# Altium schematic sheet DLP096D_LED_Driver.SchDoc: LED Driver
size 431 x 279 mm; Date: Not shown in title block; ApprovedBy: Not shown in title block; CheckedBy: Not shown in title block; Author: Not shown in title block; CompanyName: Not shown in title block; Engineer: Not shown in title block; Organization: Not shown in title block; Address1: Not shown in title block; Address2: Not shown in title block; Address3: Not shown in title block; Address4: Not shown in title block; DocumentNumber: 9; Revision: Use project parameter SCH_Rev; SheetNumber: 9; SheetTotal: 10; PageSetup: Record=PageOptions¦CenterHorizontal=True¦CenterVertical=True¦PrintScale=1.00¦XCorrection=1.00¦YCorrection=1.00¦PrintKind=0¦BorderSize=5000000¦LeftOffset=0¦BottomOffset=0¦Orientation=2¦PaperLength=1000¦PaperWidth=1000¦Scale=100¦PaperSource=15¦PrintQuality=600¦MediaType=1¦DitherType=10¦PaperKind=Letter¦PrintScaleMode=1
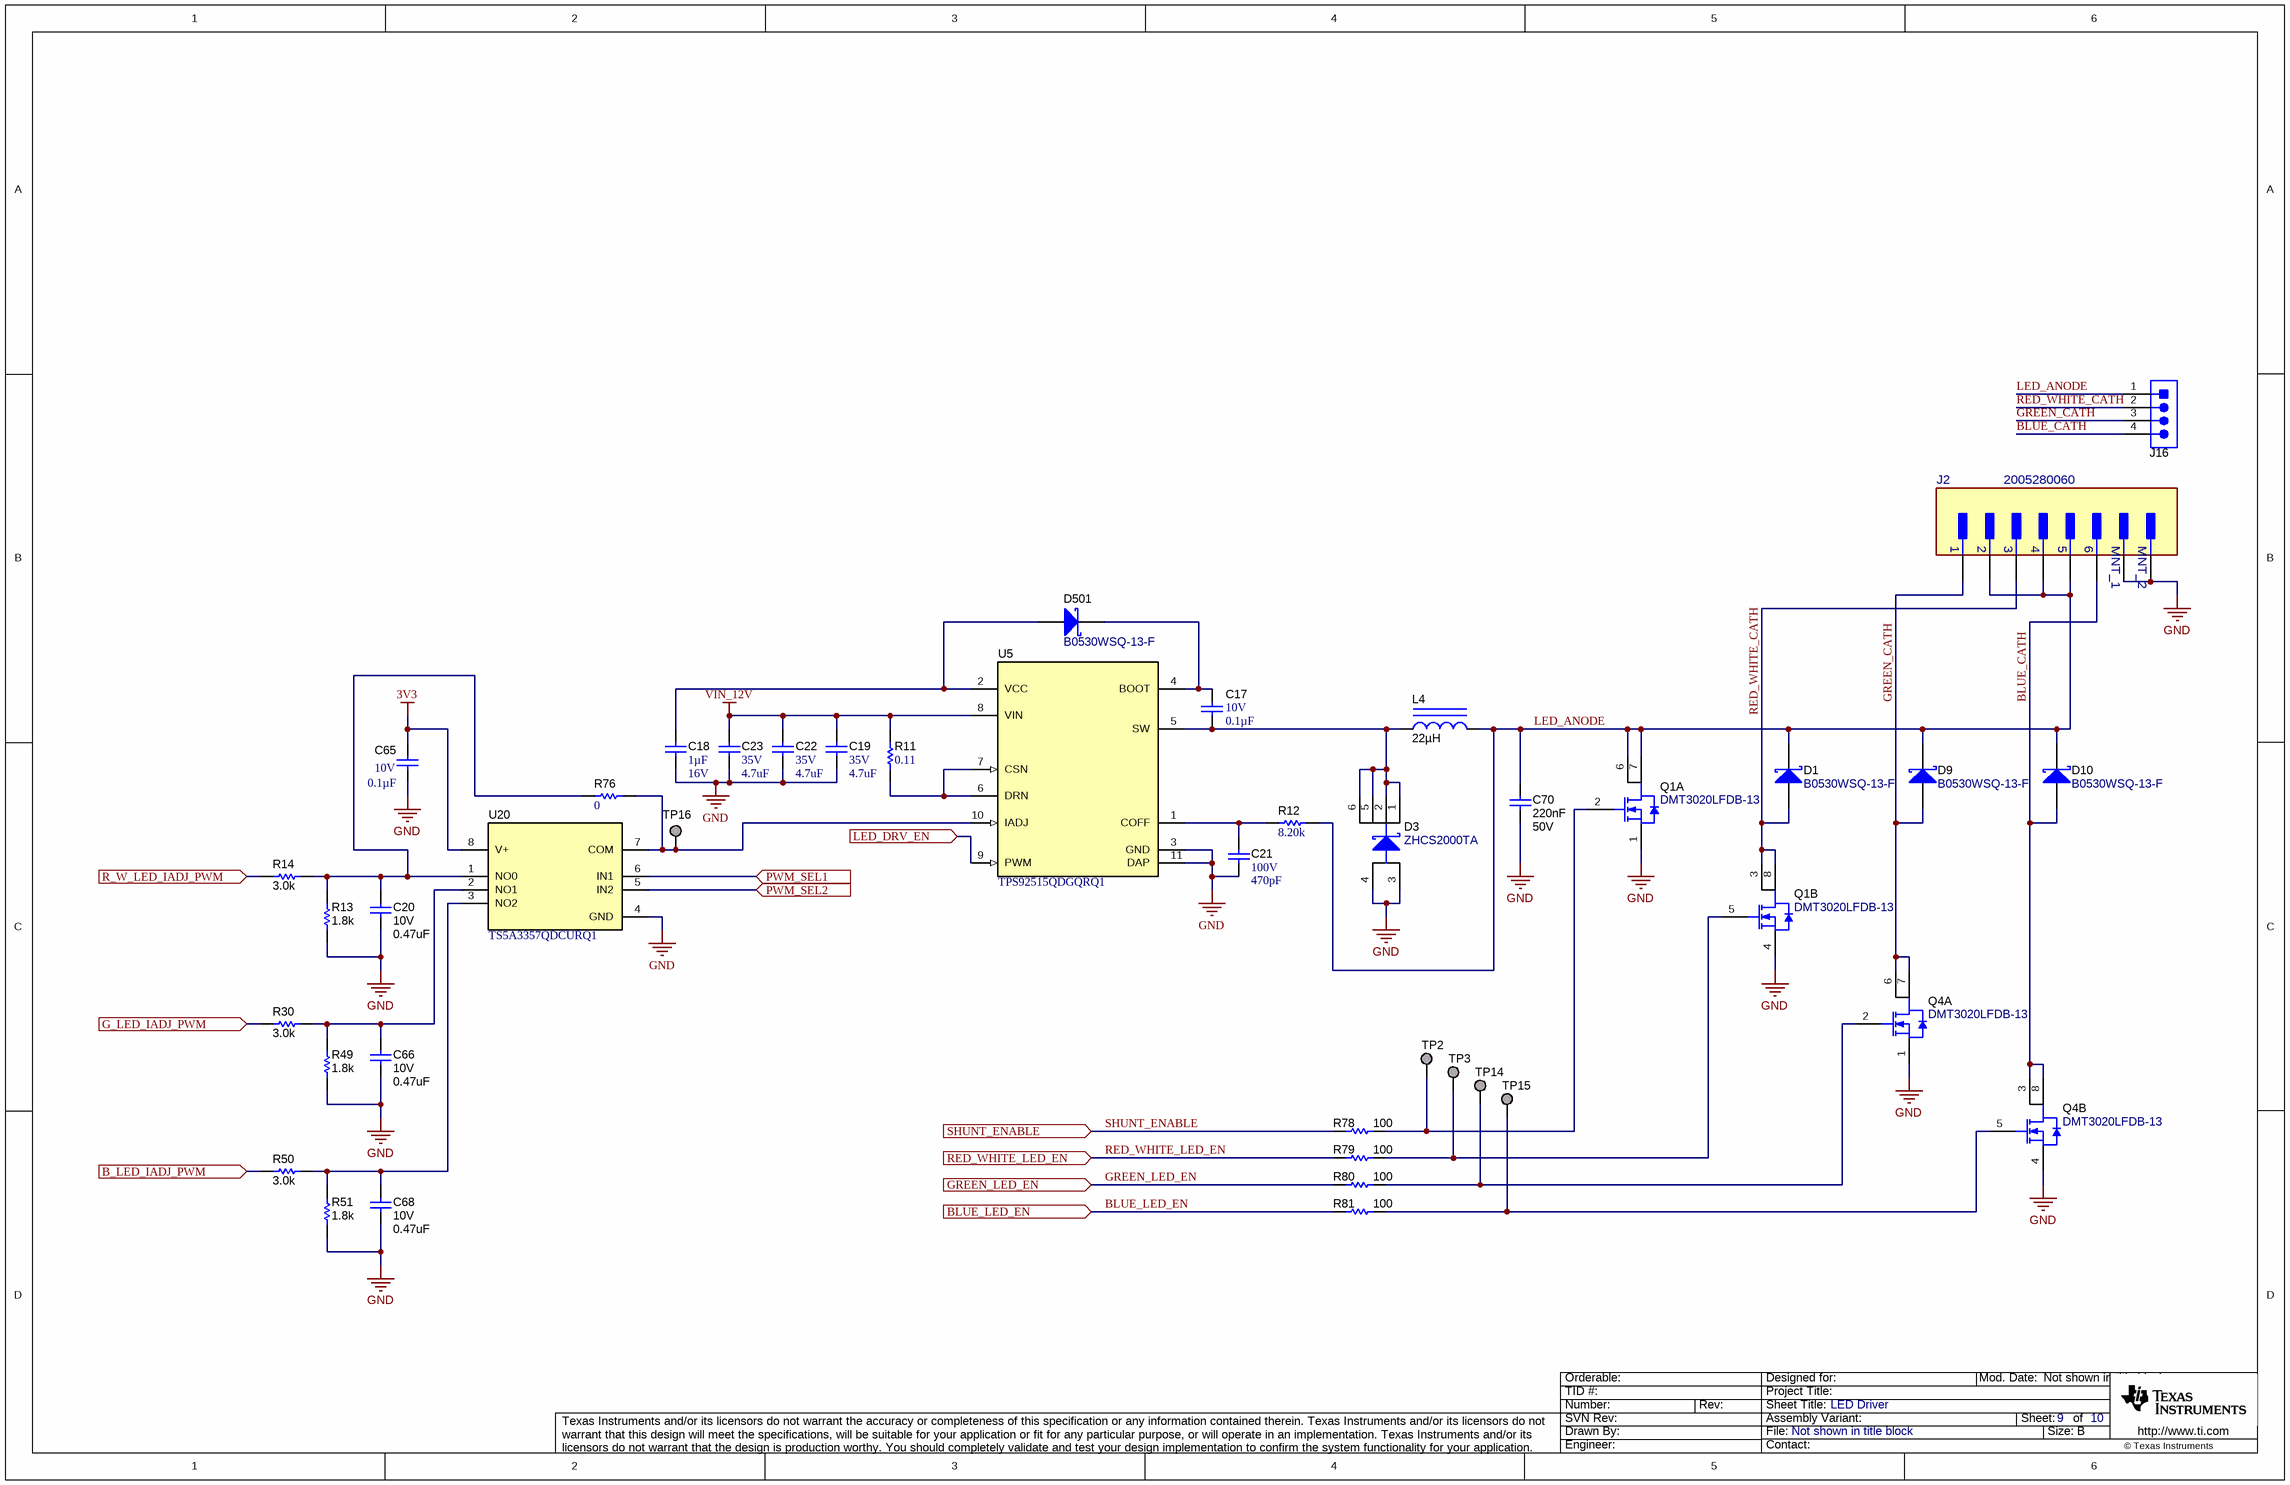
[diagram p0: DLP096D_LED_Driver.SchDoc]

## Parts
C17  VDC_V: 10V  ValueDisplayed: 0.1µF  [0201_033]  (hidden comment: GRM033R61A104KE84D)
C18  Cap_F: 1µF  VDC_V: 16V  [0603]  (hidden comment: CGA3E1X7R1C105K080AC)
C19  VDC_V: 35V  ValueDisplayed: 4.7uF  [0603]  (hidden comment: C1608X5R1V475K080AC)
C20  VDC_V: 10V  ValueDisplayed: 0.47uF  [0402L]  (hidden comment: GRT155R71A474KE01D)
C21  VDC_V: 100V  ValueDisplayed: 470pF  [0603]  (hidden comment: C1608C0G2A471J)
C22  VDC_V: 35V  ValueDisplayed: 4.7uF  [0603]  (hidden comment: C1608X5R1V475K080AC)
C23  VDC_V: 35V  ValueDisplayed: 4.7uF  [0603]  (hidden comment: C1608X5R1V475K080AC)
C65  VDC_V: 10V  ValueDisplayed: 0.1µF  [0402L]  (hidden comment: C0402C104K8RACTU)
C66  VDC_V: 10V  ValueDisplayed: 0.47uF  [0402L]  (hidden comment: GRT155R71A474KE01D)
C68  VDC_V: 10V  ValueDisplayed: 0.47uF  [0402L]  (hidden comment: GRT155R71A474KE01D)
C70  Cap_F: 220nF  VDC_V: 50V  [0603L]  (hidden comment: GCM188R71E104KA57D)
D1  B0530WSQ-13-F  [SOD-323]
D3  ZHCS2000TA  [SOT-26]
D9  B0530WSQ-13-F  [SOD-323]
D10  B0530WSQ-13-F  [SOD-323]
D501  B0530WSQ-13-F  [SOD-323]
J2  2005280060  [FP-2005280060_CONN_11MM2_5MM25-MFG]
J16  TSW-104-07-G-S  [TSW-104-07-G-S]  (value not drawn)
L4  ValueDisplayed: 22µH  [SRN5040TA]  (hidden comment: SRN5040TA-220M)
Q1  DMT3020LFDB-13  [U-DFN2020-6_B]  (parts A,B of 2)
Q4  DMT3020LFDB-13  [U-DFN2020-6_B]  (parts A,B of 2)
R11  ValueDisplayed: 0.11  [1210]  (hidden comment: MCR25JZHFLR110)
R12  ValueDisplayed: 8.20k  [0603]  (hidden comment: RC0603FR-078K2L)
R13  ValueDisplayed: 1.8k  [0402L]  (hidden comment: CRCW04021K80JNED)
R14  ValueDisplayed: 3.0k  [0402L]  (hidden comment: CRCW04023K00JNED)
R30  ValueDisplayed: 3.0k  [0402L]  (hidden comment: CRCW04023K00JNED)
R49  ValueDisplayed: 1.8k  [0402L]  (hidden comment: CRCW04021K80JNED)
R50  ValueDisplayed: 3.0k  [0402L]  (hidden comment: CRCW04023K00JNED)
R51  ValueDisplayed: 1.8k  [0402L]  (hidden comment: CRCW04021K80JNED)
R76  ValueDisplayed: 0  [0402]  (hidden comment: MCR01MZPJ000)
R78  ValueDisplayed: 100  [0402L]  (hidden comment: ERJ-2GEJ101X)
R79  ValueDisplayed: 100  [0402L]  (hidden comment: ERJ-2GEJ101X)
R80  ValueDisplayed: 100  [0402L]  (hidden comment: ERJ-2GEJ101X)
R81  ValueDisplayed: 100  [0402L]  (hidden comment: ERJ-2GEJ101X)
TP2  TP_H0.45P0.75  [TP_H045P075]  (value not drawn)  (no BOM)
TP3  TP_H0.45P0.75  [TP_H045P075]  (value not drawn)  (no BOM)
TP14  TP_H0.45P0.75  [TP_H045P075]  (value not drawn)  (no BOM)
TP15  TP_H0.45P0.75  [TP_H045P075]  (value not drawn)  (no BOM)
TP16  TP_H0.45P0.75  [TP_H045P075]  (value not drawn)  (no BOM)
U5  TPS92515QDGQRQ1  [DGQ0010E_N]
U20  TS5A3357QDCURQ1  [DCU0008A_N]

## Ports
B_LED_IADJ_PWM (in), BLUE_LED_EN (in), G_LED_IADJ_PWM (in), GREEN_LED_EN (in), LED_DRV_EN (in), PWM_SEL1 (in), PWM_SEL2 (in), R_W_LED_IADJ_PWM (in), RED_WHITE_LED_EN (in), SHUNT_ENABLE (in)

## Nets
3V3: C65.1 U20.8(V+)
GND: C18.2 C19.2 C20.2 C21.2 C22.2 C23.2 C65.2 C66.2 C68.2 C70.2 D3.3(A) D3.4(A) J2.7(MNT_1) J2.8(MNT_2) Q1.1(S1) Q1.4(S2) Q4.1(S1) Q4.4(S2) R13.1 R49.1 R51.1 U5.3(GND) U5.11(DAP) U20.4(GND)
VIN_12V: C19.1 C22.1 C23.1 R11.2 U5.8(VIN)
B_LED_IADJ_PWM: R50.1 ; port B_LED_IADJ_PWM
BLUE_CATH: D10.2(A) J2.6 J16.4 Q4.3(D2) Q4.8(D2)
BLUE_LED_EN: R81.1 ; port BLUE_LED_EN
G_LED_IADJ_PWM: R30.1 ; port G_LED_IADJ_PWM
GREEN_CATH: D9.2(A) J2.1 J16.3 Q4.6(D1) Q4.7(D1)
GREEN_LED_EN: R80.1 ; port GREEN_LED_EN
LED_ANODE: C70.1 D1.1(K) D9.1(K) D10.1(K) J2.2 J2.4 J2.5 J16.1 L4.2 Q1.6(D1) Q1.7(D1) R12.2
LED_DRV_EN: U5.9(PWM) ; port LED_DRV_EN
PWM_SEL1: U20.6(IN1) ; port PWM_SEL1
PWM_SEL2: U20.5(IN2) ; port PWM_SEL2
R_W_LED_IADJ_PWM: R14.1 ; port R_W_LED_IADJ_PWM
RED_WHITE_CATH: D1.2(A) J2.3 J16.2 Q1.3(D2) Q1.8(D2)
RED_WHITE_LED_EN: R79.1 ; port RED_WHITE_LED_EN
SHUNT_ENABLE: R78.1 ; port SHUNT_ENABLE
NetC17_1: C17.1 D501.1(K) U5.4(BOOT)
NetC17_2: C17.2 D3.1(K) D3.2(K) D3.5(K) D3.6(K) L4.1 U5.5(SW)
NetC18_1: C18.1 D501.2(A) U5.2(VCC)
NetC20_1: C20.1 R13.2 R14.2 R76.2 U20.1(NO0)
NetC21_1: C21.1 R12.1 U5.1(COFF)
NetC66_1: C66.1 R30.2 R49.2 U20.2(NO1)
NetC68_1: C68.1 R50.2 R51.2 U20.3(NO2)
NetQ1_2: Q1.2(G1) R78.2 TP2.1
NetQ1_5: Q1.5(G2) R79.2 TP3.1
NetQ4_2: Q4.2(G1) R80.2 TP14.1
NetQ4_5: Q4.5(G2) R81.2 TP15.1
NetR11_1: R11.1 U5.6(DRN) U5.7(CSN)
NetR76_1: R76.1 TP16.1 U5.10(IADJ) U20.7(COM)

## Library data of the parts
C17 = CMP-0086059-1: CAP, CERM, 0.1 µF, 10 V,+/- 10%, X5R, 0201; Manufacturer: MuRata; AEC Category: Q200; Cap_F: 100nF; Value: 0.1uF; SizeY_mm: 0.3; AEC Qualified: N; SizeAreaWB_mm2: 2.08; Cap_Case: 0201; SizeArea_mm2: 0.18; SizeZ_mm: 0.33; SizeX_mm: 0.6; TaMax_C: 85°C; TaMin_C: -55°C; U/M: EA
C18 = CMP-0079607-1: CAP, CERM, 1 µF, 16 V,+/- 10%, X7R, AEC-Q200 Grade 1, 0603; Manufacturer: TDK; TaMin_C: -55°C; Polarized: N; SizeAreaWB_mm2: 4.68; U/M: EA; Value: 1uF; TaMax_C: 125°C; SizeZ_mm: 1; SizeX_mm: 1.6; SizeY_mm: 0.8; SizeArea_mm2: 1.28; AEC Qualified: Y; AEC Category: Q200
C19 C22 C23 = CMP-0007022-5: CAP, CERM, 4.7 uF, 35 V, +/- 10%, X5R, 0603; Manufacturer: TDK; TaMin_C: -55°C; ESR_ohm: 3.728m; Polarized: N; SizeAreaWB_mm2: 4.68; Value1: 0.003728 ohm; U/M: EA; Value: 4.7uF; TaMax_C: 85°C; SizeZ_mm: 1; SizeX_mm: 1.6; SizeY_mm: 0.8; SizeArea_mm2: 1.28; Cap_F: 4.7µF; IRMS_A: 2.6936A; AEC Category: Q200
C20 C66 C68 = CMP-0006350-2: CAP, CERM, 0.47 uF, 10 V, +/- 10%, X7R, AEC-Q200 Grade 1, 0402; Manufacturer: MuRata; TaMin_C: -55°C; Polarized: N; SizeAreaWB_mm2: 3; Value1: Unknown; U/M: EA; Value: 0.1uF; TaMax_C: 125°C; SizeZ_mm: 0.6; SizeX_mm: 1; SizeY_mm: 0.5; Cap_Case: 0402; AEC Qualified: Y; Cap_F: 100nF; AEC Category: Q200
C21 = CMP-0006995-4: CAP, CERM, 470 pF, 100 V, +/- 5%, C0G/NP0, 0603; Manufacturer: TDK; TaMin_C: -55°C; ESR_ohm: 71.4m; Polarized: N; SizeAreaWB_mm2: 4.68; Value1: 0.0714 ohm; U/M: EA; Value: 470pF; TaMax_C: 125°C; SizeZ_mm: 1; SizeX_mm: 1.6; SizeY_mm: 0.8; SizeArea_mm2: 1.28; AEC Category: Q200
C65 = CMP-0078241-1: CAP, CERM, 0.1 µF, 10 V,+/- 10%, X7R, 0402; Manufacturer: Kemet; TaMin_C: -55°C; Polarized: N; SizeAreaWB_mm2: 3; U/M: EA; Value: 0.1uF; TaMax_C: 125°C; SizeZ_mm: 0.6; SizeX_mm: 1; SizeY_mm: 0.5; Cap_Case: 0402; Cap_F: 100nF; AEC Category: Q200
C70 = CMP-0007094-5: CAP, CERM, 0.22 uF, 50 V, +/- 10%, X7R, AEC-Q200 Grade 1, 0603; Manufacturer: TDK; PartNumber: CGA3E3X7R1H224K080AB; TaMin_C: -55°C; ESR_ohm: 0.021699; Polarized: N; SizeAreaWB_mm2: 4.68; Value1: 0.021699 ohm; U/M: EA; Value: 0.22uF; TaMax_C: 125°C; SizeZ_mm: 1; SizeX_mm: 1.6; SizeY_mm: 0.8; Cap_Case: 0603; SizeArea_mm2: 1.28; AEC Qualified: Y; IRMS_A: 1.12496A; AEC Category: Q200
D1 D9 D10 D501 = CMP-0079598-2: Diode, Schottky, 30 V, 0.5 A, AEC-Q101, SOD-323; Manufacturer: Diodes Inc.; SizeAreaWB_mm2: 8.695; Vr_V: 30V; SizeArea_mm2: 3.645; AEC Qualified: Y; TJmax_C: 125°C; AEC Category: Q101; Value: 30V; SizeZ_mm: 1; Io_A: 500mA; Vf_V: 400mV; SizeY_mm: 1.35; Value2: 0.4V; Value1: 0.5A; SizeX_mm: 2.7
D3 = CMP-0028830-2: Diode, Schottky, 40 V, 2 A, AEC-Q101, SOT-26; Manufacturer: Diodes Inc.; SizeZ_mm: 1; Io_A: 2A; AEC Category: Q101; Vr_V: 40V; SizeY_mm: 2.8; Value2: 0.5V; TJmax_C: 125°C; SizeAreaWB_mm2: 13.68; Value: 40V; Green_REACh: Incomplete; AEC Qualified: Y; SizeX_mm: 2.6; SizeArea_mm2: 7.28; Vf_V: 500mV; Green_Lifecycle: Not Set
J2 = CMP-0090189-1: 6 Position FFC, FPC Connector Contacts, Bottom 0.039" (1.00mm) Surface Mount, Right Angle from Molex; Conn Gender: Male; Is Female: yes; DUT-Pitch_mm: 1mm; ContactFinish: Gold,Nickel; SizeZ_mm: 4.15mm; Voltage_V: 125V; AEC Qualified: No; Current_A: 1A
J16 = CMP-0075409-2: Header, 100mil, 4x1, Gold, TH; Manufacturer: Samtec; Pitch_mm: 2.54; Cert_VDE: N; Gender: Male; Cert_CSA: Y; Voltage_V: 550V; Green_REACh: Passed; Current_A: 6.3A; Green_Lifecycle: Active; Row_Count: 1
L4 = CMP-0085685-1: Inductor, Semi-Shielded, Ferrite, 22 µH, 1.5 A, 0.1476 ohm, AEC-Q200 Grade 1, SMD; Manufacturer: Bourns; Irms: 1.5A @ 40C rise; AEC Category: Q200; DCR_ohm: 0.1476; AEC Qualified: Y; SizeArea_mm2: 24.5025; SizeY_mm: 4.95; Isat: 1.62A @ 30% inductance drop; SizeZ_mm: 4.1; SizeAreaWB_mm2: 35.4025; AEC Grade: 1; Value2: 1.5A; Value: 22uH
Q1 Q4 = CMP-0077941-1: MOSFET, 2-CH, N-CH, 30 V, 7.7 A, AEC-Q101, U-DFN2020-6; PartNumber: DMT3020LFDB-7; Manufacturer: Diodes Inc.; Alternate Manufacturer: None; ChType: N; SizeAreaWB_mm2: 9; SizeArea_mm2: 4; IdsMax_A: 7.7A; AEC Qualified: Y; VdsMax_V: 30V; Rdson45_ohm: 0.032; Vgs_V: 20V; AEC Category: Q101; Value: 30V; SizeZ_mm: 0.575; SizeY_mm: 2; Value2: ? nC; U/M: EA; Value1: 0.032 ohm
R11 = CMP-0015168-2: RES, 0.11, 1%, 0.5 W, 1210; Manufacturer: Rohm; Power_W: 500mW; TempCo: 200 ppm/C; SizeAreaWB_mm2: 14.7; Value_Code: R110; U/M: EA; Value: 0.11; EIA_Code: E96; SizeX_mm: 3.2; SizeY_mm: 2.5; SizeZ_mm: 1.35; Value2: 0.5W; SizeArea_mm2: 8; VDC_V: 0V; AEC Category: Q200
R12 = CMP-0023308-5: RES, 8.20 k, 1%, 0.1 W, 0603; Manufacturer: Yageo; Power_W: 100mW; TempCo: 100 ppm/C; Value_Code: 8k20; Value: 8.20k; Res_ohm: 8.2k; SizeX_mm: 1.6; SizeY_mm: 0.8; SizeZ_mm: 1; Value2: 0.1W; SizeArea_mm2: 1.28; AEC Qualified: N; VDC_V: 75V; AEC Category: Q200; SizeAreaWB_mm2: 4.68
R13 R49 R51 = CMP-0026858-5: RES, 1.8 k, 5%, 0.063 W, AEC-Q200 Grade 0, 0402; Manufacturer: Vishay-Dale; Power_W: 63mW; TempCo: 200 ppm/C; Value_Code: 1k80; Value: 1.8k; EIA_Code: E24; SizeX_mm: 1; SizeY_mm: 0.5; SizeZ_mm: 0.6; Value2: 0.063W; AEC Qualified: Y; VDC_V: 50V; AEC Category: Q200; AEC Grade: 0
R14 R30 R50 = CMP-0026917-5: RES, 3.0 k, 5%, 0.063 W, AEC-Q200 Grade 0, 0402; Manufacturer: Vishay-Dale; Power_W: 63mW; TempCo: 200 ppm/C; Value_Code: 3k00; Value: 3.0k; EIA_Code: E24; Res_ohm: 3k; SizeX_mm: 1; SizeY_mm: 0.5; SizeZ_mm: 0.6; Value2: 0.063W; AEC Qualified: Y; VDC_V: 50V; AEC Category: Q200; AEC Grade: 0
R76 = CMP-0027002-2: RES, 0, 5%, 0.063 W, 0402; Manufacturer: Rohm; Power_W: 63mW; TempCo: 500 ppm/C; Value_Code: 0000; U/M: EA; Value: 0; EIA_Code: E24; SizeX_mm: 1; SizeY_mm: 0.5; SizeZ_mm: 0.6; Value2: 0.063W; VDC_V: 50V; AEC Category: Q200
R78-R81 = CMP-0026993-2: RES, 100, 5%, 0.1 W, AEC-Q200 Grade 0, 0402; Manufacturer: Panasonic; Power_W: 100mW; TempCo: 200 ppm/C; Value_Code: 100R; U/M: EA; Value: 100; EIA_Code: E24; SizeX_mm: 1; SizeY_mm: 0.5; SizeZ_mm: 0.6; Value2: 0.1W; AEC Qualified: Y; AEC Grade: 0; AEC Category: Q200
TP2 TP3 TP14-TP16 = CMP-0003719-1: Testpoint; Manufacturer: Texas Instruments; CompType: Pad
U5 = CMP-0073710-1: 2A LED Driver with Integrated NFET, High-Side Current Sense, and Shunt PWM Dimming Capable, DGQ0010E (VSSOP-10); Alternate PartNumber: TPS92515QDGQQ1; Alternate Manufacturer: Texas Instruments; Green_Lifecycle: Active; SizeAreaWB_mm2: 23.52; Green_REACh: Passed; U/M: EA; SizeZ_mm: 1.1; SizeX_mm: 4.88; SizeY_mm: 3.0; SizeArea_mm2: 14.64; CompType: IC
U20 = CMP-0860295-1: Automotive Catalog Single 5-Ohm SP3T Analog Switch 5-V/3.3-V 3:1 Analog Multiplexer/Demultiplexer, DCU0008A (VSSOP-8); Alternate Manufacturer: Texas Instruments; CompType: IC; SizeArea_mm2: 6.4; AEC Category: Q200; SizeZ_mm: 0.9; SizeX_mm: 3.2; SizeY_mm: 2; AEC Qualified: Y; SizeAreaWB_mm2: 12.6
